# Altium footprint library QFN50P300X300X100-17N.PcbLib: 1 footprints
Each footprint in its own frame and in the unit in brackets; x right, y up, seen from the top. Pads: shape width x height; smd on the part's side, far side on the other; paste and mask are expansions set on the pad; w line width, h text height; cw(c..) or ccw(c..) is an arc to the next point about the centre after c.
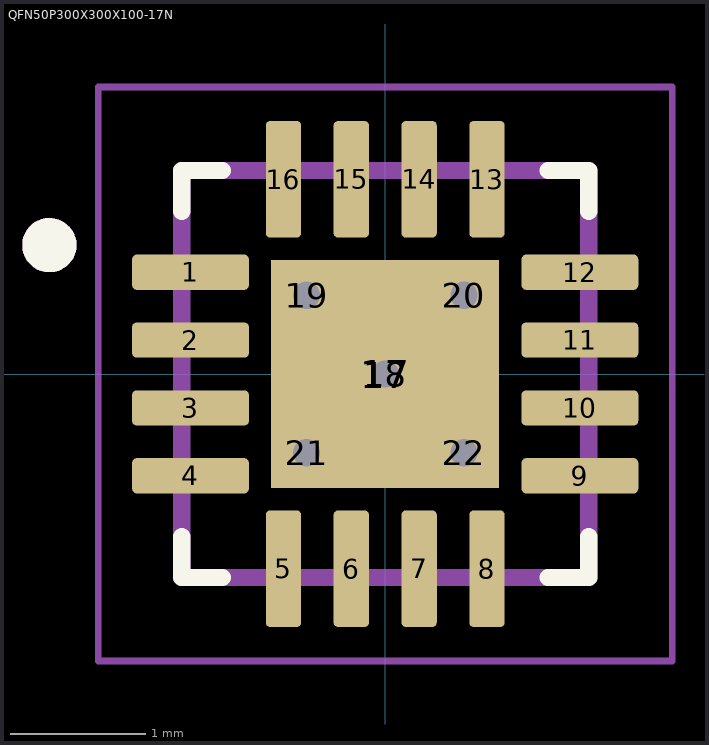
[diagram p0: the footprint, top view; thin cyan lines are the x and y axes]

## QFN50P300X300X100-17N [mm]
pads (22):
  rrect25% 0.86x0.26 smd: 1(-1.435,0.75) 2(-1.435,0.25) 3(-1.435,-0.25) 4(-1.435,-0.75) 9(1.435,-0.75) 10(1.435,-0.25) 11(1.435,0.25) 12(1.435,0.75)
  rrect25% 0.26x0.86 smd: 5(-0.75,-1.435) 6(-0.25,-1.435) 7(0.25,-1.435) 8(0.75,-1.435) 13(0.75,1.435) 14(0.25,1.435) 15(-0.25,1.435) 16(-0.75,1.435)
  rect 1.68x1.68 smd paste-2: 17(0,0)
  round 0.4 hole 0.2 mask+0: 18(0,0) 19(-0.58,0.58) 20(0.58,0.58) 21(-0.58,-0.58) 22(0.58,-0.58)
Top Overlay:
  circle w0.2: c-2.475,0.95 r0.1
  lines w0.127: -1.5,-1.2 -1.5,-1.5 -1.2,-1.5 ; -1.5,1.2 -1.5,1.5 -1.2,1.5 ; 1.2,-1.5 1.5,-1.5 1.5,-1.2 ; 1.2,1.5 1.5,1.5 1.5,1.2
Top Paste:
  region: 0.53,-0.53 -0.53,-0.53 -0.53,0.53 0.53,0.53
Mechanical 13:
  circle w0.2: c-2.475,0.95 r0.1
  lines w0.127: -1.5,-1.5 -1.5,1.5 1.5,1.5 1.5,-1.5 -1.5,-1.5
Mechanical 15:
  lines w0.05: -2.115,-2.115 -2.115,2.115 2.115,2.115 2.115,-2.115 -2.115,-2.115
